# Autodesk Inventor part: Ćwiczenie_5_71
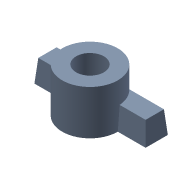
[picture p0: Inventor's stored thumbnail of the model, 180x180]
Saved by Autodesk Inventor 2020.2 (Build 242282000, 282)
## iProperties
Created: 2005-08
Part Number: Ćwiczenie_5_71
Document SubType Name: Modeling
Designer: F.Stasiak
Manufacturer: Standard
Standards Organization: Custom
Density: 1 g/cm^3
Material: Ogólny
Appearance: Stalowoniebieska - jasna
Manager: www.cadconsulting.pl
Company: Fabian Stasiak CAD Consulting
Author: F.Stasiak
Subject: Zbiór ćwiczeń. Autodesk Inventor 2020. Kurs podstawowy
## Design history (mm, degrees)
sketch "Szkic1"
  geometry: L1 (0, 0)-(100, 0); L2 (100, 0)-(100, 20); L3 (100, 20)-(0, 20); L4 (0, 20)-(0, 0); L5 (0, 10)-(100, 10); C1 r 25 at (50, 0)
  constraints: 10 end point, 3 midpoint, 2 parallel, 1 centre point, 1 horizontal, 1 perpendicular
  dimensions: "d0" = 100 distance of L1.start L1.end; "d1" = 20 distance of L3.end L1.start; "d2" = 50 diameter of C1
extrude "Wyciągnięcie proste1" new body sketch "Szkic1" distance "d3" = 20; taper "d4" = -5 deg
extrude "Wyciągnięcie proste2" join sketch "Szkic1" distance "d5" = 40; taper "d6" = 0 deg
sketch "Szkic2"
  geometry: C1 r 25 at (0, 0) reference; C2 r 12.5 at (0, 0)
  constraints: 1 centre point
  dimensions: "d7" = 25 diameter of C2
extrude "Wyciągnięcie proste3" cut sketch "Szkic2" distance "d8" = 40; taper "d9" = 0 deg
node "Bryła1"
node "Korpusy bryłowe"
node "Korpusy powierzchniowe"
